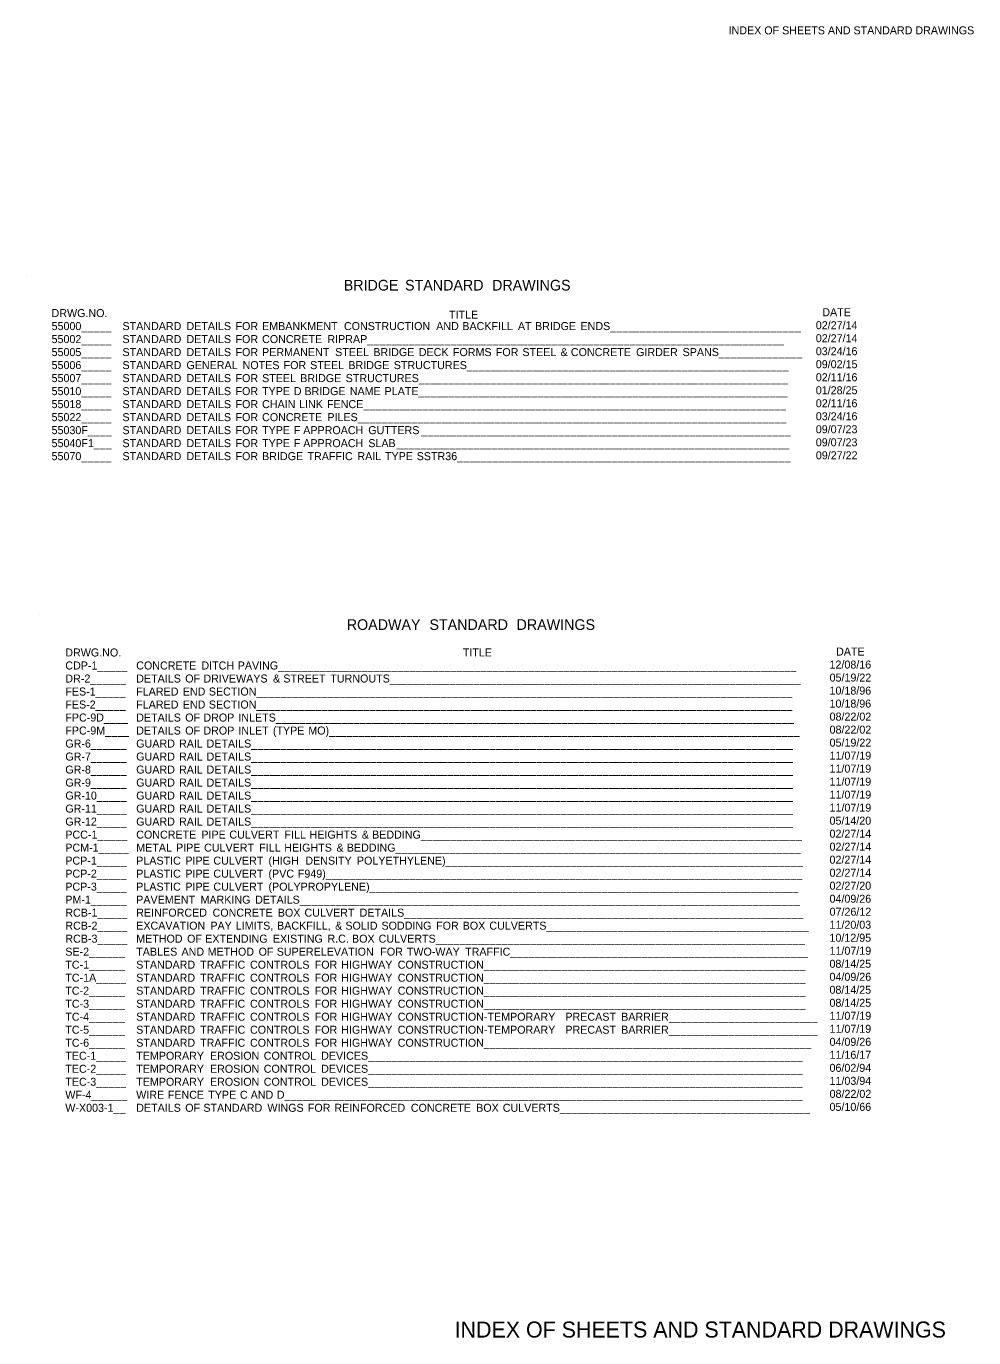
# Model space of a CAD drawing. Extents: x -1420 to 1630, y -1031 to 935.
# Drawn here: x 210 to 1630, y -1031 to 935 of the extents above; entities that cross this region are included whole.
import ezdxf

# ---------------------------------------------------------------- set-up
doc = ezdxf.new("R2010")
doc.units = 0
for name, color, linetype in [('Default', 7, 'Continuous'), ('R_Annotation', 7, 'Continuous'), ('R_Border', 7, 'Continuous')]:
    doc.layers.add(name, color=color, linetype=linetype)

msp = doc.modelspace()

# ---------------------------------------------------------------- linework, layer by layer
at = {"layer": 'Default'}
for p, q in [((209.8, 562.3), (209.8, 562.3)), ((230.4, 53.6), (230.4, 53.6))]:
    msp.add_line(p, q, dxfattribs=at)

# ---------------------------------------------------------------- texts
for s, height, p in [('BRIDGE', 16, (685.8, 539.2)), (' STANDARD', 16, (771.7, 539.2)), (' DRAWINGS', 16, (902.2, 539.2)), ('DRWG.NO.', 12, (247.8, 499.4)), ('DATE', 12, (1403.2, 500.7)), ('55000_____', 12, (247.8, 479.9)), ('STANDARD', 12, (354.1, 479.9)), (' DETAILS', 12, (445.5, 479.9)), (' FOR', 12, (519.1, 479.9)), (' EMBANKMENT', 12, (558.9, 479.9)), (' CONSTRUCTION', 12, (681.6, 479.9)), (' AND', 12, (819.9, 479.9)), ('TITLE', 12, (843.6, 497)), (' BACKFILL', 12, (859.1, 479.9)), (' AT', 12, (942.4, 479.9)), (' BRIDGE', 12, (968.1, 479.9)), (' ENDS________________________________', 12, (1036.2, 479.9)), ('02/27/14', 12, (1393.4, 481.2)), ('55002_____', 12, (247.8, 460.4)), ('STANDARD', 12, (354.1, 460.4)), (' DETAILS', 12, (445.5, 460.4)), (' FOR', 12, (519.1, 460.4)), (' CONCRETE', 12, (558.9, 460.4)), (' RIPRAP______________________________________________________________________', 12, (656.8, 460.4)), ('02/27/14', 12, (1393.4, 461.7)), ('55005_____', 12, (247.8, 440.9)), ('STANDARD', 12, (354.1, 440.9)), (' DETAILS', 12, (445.5, 440.9)), (' FOR', 12, (519.1, 440.9)), (' PERMANENT', 12, (558.9, 440.9)), (' STEEL', 12, (668.5, 440.9)), (' BRIDGE', 12, (725.7, 440.9)), (' DECK', 12, (793.8, 440.9)), (' FORMS', 12, (845, 440.9)), (' FOR', 12, (909.3, 440.9)), (' STEEL', 12, (949.1, 440.9)), (' &', 12, (1006.3, 440.9)), (' CONCRETE', 12, (1021.8, 440.9)), (' GIRDER', 12, (1119.6, 440.9)), (' SPANS______________', 12, (1189.3, 440.9)), ('03/24/16', 12, (1393.4, 442.2)), ('55006_____', 12, (247.8, 421.4)), ('STANDARD', 12, (354.1, 421.4)), (' GENERAL', 12, (445.5, 421.4)), (' NOTES', 12, (529.7, 421.4)), (' FOR', 12, (591.2, 421.4)), (' STEEL', 12, (631, 421.4)), (' BRIDGE', 12, (688.2, 421.4)), (' STRUCTURES______________________________________________________', 12, (756.3, 421.4)), ('09/02/15', 12, (1393.4, 422.7)), ('55007_____', 12, (247.8, 401.9)), ('STANDARD', 12, (354.1, 401.9)), (' DETAILS', 12, (445.5, 401.9)), (' FOR', 12, (519.1, 401.9)), (' STEEL', 12, (558.9, 401.9)), (' BRIDGE', 12, (616.1, 401.9)), (' STRUCTURES______________________________________________________________', 12, (684.2, 401.9)), ('02/11/16', 12, (1393.4, 403.2)), ('55010_____', 12, (247.8, 382.4)), ('STANDARD', 12, (354.1, 382.4)), (' DETAILS', 12, (445.5, 382.4)), (' FOR', 12, (519.1, 382.4)), (' TYPE', 12, (558.9, 382.4)), (' D', 12, (606.5, 382.4)), (' BRIDGE', 12, (622.4, 382.4)), (' NAME', 12, (690.4, 382.4)), (' PLATE______________________________________________________________', 12, (742.6, 382.4)), ('01/28/25', 12, (1393.4, 383.7)), ('55018_____', 12, (247.8, 362.9)), ('STANDARD', 12, (354.1, 362.9)), (' DETAILS', 12, (445.5, 362.9)), (' FOR', 12, (519.1, 362.9)), (' CHAIN', 12, (558.9, 362.9)), (' LINK', 12, (614.4, 362.9)), (' FENCE_______________________________________________________________________', 12, (656.3, 362.9)), ('02/11/16', 12, (1393.4, 364.2)), ('55022_____', 12, (247.8, 343.4)), ('STANDARD', 12, (354.1, 343.4)), (' DETAILS', 12, (445.5, 343.4)), (' FOR', 12, (519.1, 343.4)), (' CONCRETE', 12, (558.9, 343.4)), (' PILES________________________________________________________________________', 12, (656.8, 343.4)), ('03/24/16', 12, (1393.4, 344.7)), ('55030F____', 12, (247.8, 323.9)), ('STANDARD', 12, (354.1, 323.9)), (' DETAILS', 12, (445.5, 323.9)), (' FOR', 12, (519.1, 323.9)), (' TYPE', 12, (558.9, 323.9)), (' F', 12, (606.5, 323.9)), (' APPROACH', 12, (620.6, 323.9)), (' GUTTERS', 12, (718.1, 323.9)), ('09/07/23', 12, (1393.4, 325.2)), ('55040F1___', 12, (247.8, 304.4)), ('STANDARD', 12, (354.1, 304.4)), (' DETAILS', 12, (445.5, 304.4)), (' FOR', 12, (519.1, 304.4)), (' TYPE', 12, (558.9, 304.4)), (' F', 12, (606.5, 304.4)), (' APPROACH', 12, (620.6, 304.4)), (' SLAB', 12, (718.1, 304.4)), ('______________________________________________________________', 12, (802, 323.9)), ('09/07/23', 12, (1393.4, 305.7)), ('55070_____', 12, (247.8, 284.9)), ('STANDARD', 12, (354.1, 284.9)), (' DETAILS', 12, (445.5, 284.9)), (' FOR', 12, (519.1, 284.9)), (' BRIDGE', 12, (558.9, 284.9)), (' TRAFFIC', 12, (627, 284.9)), (' RAIL', 12, (701.8, 284.9)), (' TYPE', 12, (743.1, 284.9)), ('__________________________________________________________________', 12, (764.7, 304.4)), (' SSTR36________________________________________________________', 12, (790.7, 284.9)), ('09/27/22', 12, (1393.5, 286.2)), ('ROADWAY', 16, (690.3, 30.4)), (' STANDARD', 16, (808.3, 30.4)), (' DRAWINGS', 16, (938.9, 30.4)), ('DRWG.NO.', 12, (268.4, -9.4)), ('TITLE', 12, (864.2, -9.4)), ('DATE', 12, (1423.8, -8)), ('CDP-1_____', 12, (268.4, -28.9)), ('CONCRETE', 12, (374.7, -28.9)), (' DITCH', 12, (467.9, -28.9)), (' PAVING_______________________________________________________________________________________', 12, (522.4, -28.9)), ('12/08/16', 12, (1414, -27.5)), ('DR-2______', 12, (268.4, -48.4)), ('DETAILS', 12, (374.7, -48.4)), (' OF', 12, (443.7, -48.4)), (' DRIVEWAYS', 12, (470.9, -48.4)), (' &', 12, (575.3, -48.4)), (' STREET', 12, (590.7, -48.4)), (' TURNOUTS_____________________________________________________________________', 12, (661.2, -48.4)), ('05/19/22', 12, (1414.1, -47)), ('FES-1_____', 12, (268.4, -67.9)), ('FLARED', 12, (374.7, -67.9)), (' END', 12, (440, -67.9)), (' SECTION__________________________________________________________________________________________', 12, (479.1, -67.9)), ('10/18/96', 12, (1414, -66.5)), ('FES-2_____', 12, (268.4, -87.4)), ('FLARED', 12, (374.7, -87.4)), (' END', 12, (440, -87.4)), (' SECTION__________________________________________________________________________________________', 12, (479.1, -87.4)), ('10/18/96', 12, (1414, -86)), ('FPC-9D____', 12, (268.4, -106.9)), ('DETAILS', 12, (374.7, -106.9)), (' OF', 12, (443.7, -106.9)), (' DROP', 12, (470.9, -106.9)), (' INLETS_______________________________________________________________________________________', 12, (523.3, -106.9)), ('08/22/02', 12, (1414.1, -105.5)), ('FPC-9M____', 12, (268.4, -126.4)), ('DETAILS', 12, (374.7, -126.4)), (' OF', 12, (443.7, -126.4)), (' DROP', 12, (470.9, -126.4)), (' INLET', 12, (523.3, -126.4)), (' (TYPE', 12, (575.1, -126.4)), (' MO)_______________________________________________________________________________', 12, (628.2, -126.4)), ('08/22/02', 12, (1414.1, -125)), ('GR-6______', 12, (268.4, -145.9)), ('GUARD', 12, (374.7, -145.9)), (' RAIL', 12, (434.4, -145.9)), (' DETAILS___________________________________________________________________________________________', 12, (475.7, -145.9)), ('05/19/22', 12, (1414.1, -144.5)), ('GR-7______', 12, (268.4, -165.4)), ('GUARD', 12, (374.7, -165.4)), (' RAIL', 12, (434.4, -165.4)), (' DETAILS___________________________________________________________________________________________', 12, (475.7, -165.4)), ('11/07/19', 12, (1414, -164)), ('GR-8______', 12, (268.4, -184.9)), ('GUARD', 12, (374.7, -184.9)), (' RAIL', 12, (434.4, -184.9)), (' DETAILS___________________________________________________________________________________________', 12, (475.7, -184.9)), ('11/07/19', 12, (1414, -183.5)), ('GR-9______', 12, (268.4, -204.4)), ('GUARD', 12, (374.7, -204.4)), (' RAIL', 12, (434.4, -204.4)), (' DETAILS___________________________________________________________________________________________', 12, (475.7, -204.4)), ('11/07/19', 12, (1414, -203)), ('GR-10_____', 12, (268.4, -223.9)), ('GUARD', 12, (374.7, -223.9)), (' RAIL', 12, (434.4, -223.9)), (' DETAILS___________________________________________________________________________________________', 12, (475.7, -223.9)), ('11/07/19', 12, (1414, -222.5)), ('GR-11_____', 12, (268.4, -243.4)), ('GUARD', 12, (374.7, -243.4)), (' RAIL', 12, (434.4, -243.4)), (' DETAILS___________________________________________________________________________________________', 12, (475.7, -243.4)), ('11/07/19', 12, (1414, -242)), ('GR-12_____', 12, (268.4, -262.9)), ('GUARD', 12, (374.7, -262.9)), (' RAIL', 12, (434.4, -262.9)), (' DETAILS___________________________________________________________________________________________', 12, (475.7, -262.9)), ('05/14/20', 12, (1414, -261.5)), ('PCC-1_____', 12, (268.4, -282.4)), ('CONCRETE', 12, (374.7, -282.4)), (' PIPE', 12, (467.9, -282.4)), (' CULVERT', 12, (509.9, -282.4)), (' FILL', 12, (592.5, -282.4)), (' HEIGHTS', 12, (630.1, -282.4)), (' &', 12, (708.4, -282.4)), (' BEDDING________________________________________________________________', 12, (723.8, -282.4)), ('02/27/14', 12, (1414, -281)), ('PCM-1_____', 12, (268.4, -301.9)), ('METAL', 12, (374.7, -301.9)), (' PIPE', 12, (430, -301.9)), (' CULVERT', 12, (472, -301.9)), (' FILL', 12, (554.6, -301.9)), (' HEIGHTS', 12, (592.2, -301.9)), (' &', 12, (670.5, -301.9)), (' BEDDING____________________________________________________________________', 12, (685.9, -301.9)), ('02/27/14', 12, (1414, -300.5)), ('PCP-1_____', 12, (268.4, -321.4)), ('PLASTIC', 12, (374.7, -321.4)), (' PIPE', 12, (443.9, -321.4)), (' CULVERT', 12, (485.9, -321.4)), (' (HIGH', 12, (568.5, -321.4)), ('  DENSITY', 12, (619.3, -321.4)), (' POLYETHYLENE)____________________________________________________________', 12, (701.1, -321.4)), ('02/27/14', 12, (1414, -320)), ('PCP-2_____', 12, (268.4, -340.9)), ('PLASTIC', 12, (374.7, -340.9)), (' PIPE', 12, (443.9, -340.9)), (' CULVERT', 12, (485.9, -340.9)), (' (PVC', 12, (568.5, -340.9)), (' F949)________________________________________________________________________________', 12, (612.5, -340.9)), ('02/27/14', 12, (1414, -339.5)), ('PCP-3_____', 12, (268.4, -360.4)), ('PLASTIC', 12, (374.7, -360.4)), (' PIPE', 12, (443.9, -360.4)), (' CULVERT', 12, (485.9, -360.4)), (' (POLYPROPYLENE)________________________________________________________________________', 12, (568.5, -360.4)), ('02/27/20', 12, (1414, -359)), ('PM-1______', 12, (268.4, -379.9)), ('PAVEMENT', 12, (374.7, -379.9)), (' MARKING', 12, (466.6, -379.9)), (' DETAILS____________________________________________________________________________________', 12, (548.5, -379.9)), ('04/09/26', 12, (1414, -378.5)), ('RCB-1_____', 12, (268.4, -399.4)), ('REINFORCED', 12, (374.7, -399.4)), (' CONCRETE', 12, (484.7, -399.4)), (' BOX', 12, (582.5, -399.4)), (' CULVERT', 12, (622.5, -399.4)), (' DETAILS___________________________________________________________________', 12, (705.1, -399.4)), ('07/26/12', 12, (1414.1, -398)), ('RCB-2_____', 12, (268.4, -418.9)), ('EXCAVATION', 12, (374.7, -418.9)), (' PAY', 12, (481.4, -418.9)), (' LIMITS,', 12, (519.5, -418.9)), (' BACKFILL,', 12, (581.4, -418.9)), (' &', 12, (668.4, -418.9)), (' SOLID', 12, (683.8, -418.9)), (' SODDING', 12, (737.9, -418.9)), (' FOR', 12, (819.8, -418.9)), (' BOX', 12, (859.6, -418.9)), (' CULVERTS____________________________________________', 12, (899.6, -418.9)), ('11/20/03', 12, (1414, -417.5)), ('RCB-3_____', 12, (268.4, -438.4)), ('METHOD', 12, (374.7, -438.4)), (' OF', 12, (446.5, -438.4)), (' EXTENDING', 12, (473.6, -438.4)), (' EXISTING', 12, (575.1, -438.4)), (' R.C.', 12, (656.9, -438.4)), (' BOX', 12, (693.7, -438.4)), (' CULVERTS______________________________________________________________', 12, (733.6, -438.4)), ('10/12/95', 12, (1413.9, -437)), ('SE-2______', 12, (268.4, -457.9)), ('TABLES', 12, (374.7, -457.9)), (' AND', 12, (438.1, -457.9)), (' METHOD', 12, (477.3, -457.9)), (' OF', 12, (553.7, -457.9)), (' SUPERELEVATION', 12, (580.9, -457.9)), (' FOR', 12, (736.1, -457.9)), (' TWO-WAY', 12, (775.9, -457.9)), (' TRAFFIC__________________________________________________', 12, (863.3, -457.9)), ('11/07/19', 12, (1414, -456.5)), ('TC-1______', 12, (268.4, -477.4)), ('STANDARD', 12, (374.7, -477.4)), (' TRAFFIC', 12, (466, -477.4)), (' CONTROLS', 12, (540.8, -477.4)), (' FOR', 12, (637.8, -477.4)), (' HIGHWAY', 12, (677.6, -477.4)), (' CONSTRUCTION______________________________________________________', 12, (762.2, -477.4)), ('08/14/25', 12, (1413.9, -476)), ('TC-1A_____', 12, (268.4, -496.9)), ('STANDARD', 12, (374.7, -496.9)), (' TRAFFIC', 12, (466, -496.9)), (' CONTROLS', 12, (540.8, -496.9)), (' FOR', 12, (637.8, -496.9)), (' HIGHWAY', 12, (677.6, -496.9)), (' CONSTRUCTION______________________________________________________', 12, (762.2, -496.9)), ('04/09/26', 12, (1414, -495.5)), ('TC-2______', 12, (268.4, -516.4)), ('STANDARD', 12, (374.7, -516.4)), (' TRAFFIC', 12, (466, -516.4)), (' CONTROLS', 12, (540.8, -516.4)), (' FOR', 12, (637.8, -516.4)), (' HIGHWAY', 12, (677.6, -516.4)), (' CONSTRUCTION______________________________________________________', 12, (762.2, -516.4)), ('08/14/25', 12, (1413.9, -515)), ('TC-3______', 12, (268.4, -535.9)), ('STANDARD', 12, (374.7, -535.9)), (' TRAFFIC', 12, (466, -535.9)), (' CONTROLS', 12, (540.8, -535.9)), (' FOR', 12, (637.8, -535.9)), (' HIGHWAY', 12, (677.6, -535.9)), (' CONSTRUCTION______________________________________________________', 12, (762.2, -535.9)), ('08/14/25', 12, (1413.9, -534.5)), ('TC-4______', 12, (268.4, -555.4)), ('STANDARD', 12, (374.7, -555.4)), (' TRAFFIC', 12, (466, -555.4)), (' CONTROLS', 12, (540.8, -555.4)), (' FOR', 12, (637.8, -555.4)), (' HIGHWAY', 12, (677.6, -555.4)), (' CONSTRUCTION-TEMPORARY', 12, (762.2, -555.4)), (' PRECAST', 12, (1013.6, -555.4)), (' BARRIER_________________________', 12, (1097.2, -555.4)), ('11/07/19', 12, (1414, -554)), ('TC-5______', 12, (268.4, -574.9)), ('STANDARD', 12, (374.7, -574.9)), (' TRAFFIC', 12, (466, -574.9)), (' CONTROLS', 12, (540.8, -574.9)), (' FOR', 12, (637.8, -574.9)), (' HIGHWAY', 12, (677.6, -574.9)), (' CONSTRUCTION-TEMPORARY', 12, (762.2, -574.9)), (' PRECAST', 12, (1013.6, -574.9)), (' BARRIER_________________________', 12, (1097.2, -574.9)), ('11/07/19', 12, (1414, -573.5)), ('TC-6______', 12, (268.4, -594.4)), ('STANDARD', 12, (374.7, -594.4)), (' TRAFFIC', 12, (466, -594.4)), (' CONTROLS', 12, (540.8, -594.4)), (' FOR', 12, (637.8, -594.4)), (' HIGHWAY', 12, (677.6, -594.4)), (' CONSTRUCTION_______________________________________________________', 12, (762.2, -594.4)), ('04/09/26', 12, (1414, -593)), ('TEC-1_____', 12, (268.4, -613.9)), ('TEMPORARY', 12, (374.7, -613.9)), (' EROSION', 12, (480.8, -613.9)), (' CONTROL', 12, (561.4, -613.9)), (' DEVICES_________________________________________________________________________', 12, (647.4, -613.9)), ('11/16/17', 12, (1414, -612.5)), ('TEC-2_____', 12, (268.4, -633.4)), ('TEMPORARY', 12, (374.7, -633.4)), (' EROSION', 12, (480.8, -633.4)), (' CONTROL', 12, (561.4, -633.4)), (' DEVICES_________________________________________________________________________', 12, (647.4, -633.4)), ('06/02/94', 12, (1414, -632)), ('TEC-3_____', 12, (268.4, -652.9)), ('TEMPORARY', 12, (374.7, -652.9)), (' EROSION', 12, (480.8, -652.9)), (' CONTROL', 12, (561.4, -652.9)), (' DEVICES_________________________________________________________________________', 12, (647.4, -652.9)), ('11/03/94', 12, (1414, -651.5)), ('WF-4______', 12, (268.4, -672.4)), ('WIRE', 12, (374.7, -672.4)), (' FENCE', 12, (417.6, -672.4)), (' TYPE', 12, (478.2, -672.4)), (' C', 12, (525.7, -672.4)), (' AND', 12, (541.8, -672.4)), (' D_______________________________________________________________________________________', 12, (581, -672.4)), ('08/22/02', 12, (1414.1, -671)), ('W-X003-1__', 12, (268.4, -691.9)), ('DETAILS', 12, (374.7, -691.9)), (' OF', 12, (443.7, -691.9)), (' STANDARD', 12, (470.9, -691.9)), (' WINGS', 12, (566.9, -691.9)), (' FOR', 12, (627.5, -691.9)), (' REINFORCED', 12, (667.3, -691.9)), (' CONCRETE', 12, (781.9, -691.9)), (' BOX', 12, (879.8, -691.9)), (' CULVERTS__________________________________________', 12, (919.7, -691.9)), ('05/10/66', 12, (1414, -690.5))]:
    msp.add_text(s, height=height, dxfattribs=at).set_placement(p)
at = {"layer": 'R_Annotation'}
msp.add_text('INDEX OF SHEETS AND STANDARD DRAWINGS', height=24, dxfattribs=at).set_placement((852, -1030.3))
at = {"layer": 'R_Border'}
msp.add_text('INDEX OF SHEETS AND STANDARD DRAWINGS', height=12, dxfattribs=at).set_placement((1262.7, 923.2))

doc.saveas('drawing.dxf')
